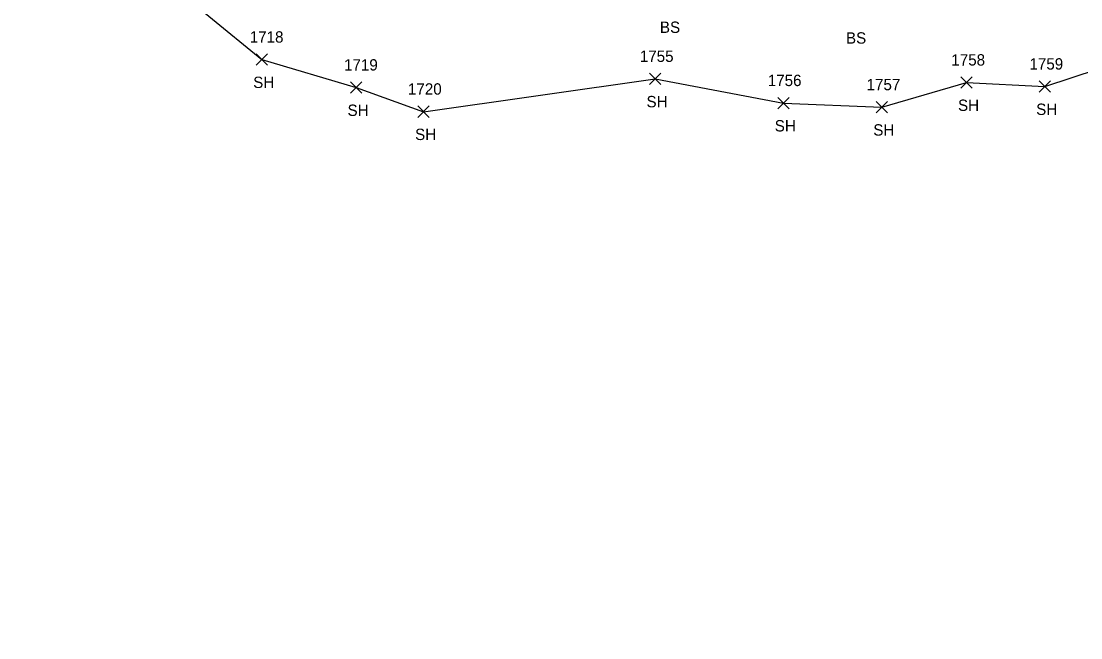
# Model space of a CAD drawing. Extents: x 1754529 to 1755810, y 621660 to 624656.
# Drawn here: x 1755027.6 to 1755214.3, y 623764.8 to 623873.5 of the extents above; entities that cross this region are included whole.
import ezdxf

# ---------------------------------------------------------------- set-up
doc = ezdxf.new("R2010")
doc.units = 0
for name, color, linetype in [('L_A', 7, 'Continuous'), ('L_I', 7, 'Continuous'), ('L_TIC', 7, 'Continuous'), ('LSOGP', 7, 'Continuous')]:
    doc.layers.add(name, color=color, linetype=linetype)

msp = doc.modelspace()

# ---------------------------------------------------------------- linework, layer by layer
at = {"layer": 'L_TIC'}
for points in [[(1755069.03, 623865.74), (1755071.03, 623867.74)], [(1755071.03, 623865.74), (1755069.03, 623867.74)], [(1755138.32, 623862.34), (1755140.32, 623864.34)], [(1755140.32, 623862.34), (1755138.32, 623864.34)], [(1755085.65, 623860.82), (1755087.65, 623862.82)], [(1755087.65, 623860.82), (1755085.65, 623862.82)], [(1755193.19, 623861.7), (1755195.19, 623863.7)], [(1755195.19, 623861.7), (1755193.19, 623863.7)], [(1755206.96, 623860.99), (1755208.96, 623862.99)], [(1755208.96, 623860.99), (1755206.96, 623862.99)], [(1755160.91, 623858.08), (1755162.91, 623860.08)], [(1755162.91, 623858.08), (1755160.91, 623860.08)], [(1755178.26, 623857.35), (1755180.26, 623859.35)], [(1755180.26, 623857.35), (1755178.26, 623859.35)], [(1755097.54, 623856.57), (1755099.54, 623858.57)], [(1755099.54, 623856.57), (1755097.54, 623858.57)]]:
    msp.add_lwpolyline(points, dxfattribs=at)
at = {"layer": 'LSOGP'}
msp.add_lwpolyline([(1755004.07, 623910.86), (1755037.03, 623891.65), (1755051.38, 623882.08), (1755070.03, 623866.74), (1755086.65, 623861.82), (1755098.54, 623857.57), (1755139.32, 623863.34), (1755161.91, 623859.08), (1755179.26, 623858.35), (1755194.19, 623862.7), (1755207.96, 623861.99), (1755217.43, 623865.11), (1755235.99, 623865.05), (1755250.43, 623863.91), (1755263.55, 623860.65), (1755279.26, 623833.69), (1755282.84, 623818.8), (1755283.41, 623777.57), (1755283.62, 623765.66), (1755287.66, 623764.84), (1755327.27, 623772.06), (1755352.63, 623769.93), (1755354.61, 623769.01), (1755434.62, 623771.42)], dxfattribs=at)

# ---------------------------------------------------------------- texts
at = {"layer": 'L_A'}
for s, p in [('BS', (1755140.16, 623871.45)), ('BS', (1755172.94, 623869.56)), ('SH', (1755068.51, 623861.74)), ('SH', (1755085.13, 623856.82)), ('SH', (1755137.8, 623858.34)), ('SH', (1755192.68, 623857.7)), ('SH', (1755206.45, 623856.99)), ('SH', (1755160.39, 623854.08)), ('SH', (1755177.75, 623853.35)), ('SH', (1755097.03, 623852.57))]:
    msp.add_text(s, height=2, dxfattribs=at).set_placement(p)
at = {"layer": 'L_I'}
for s, p in [('1718', (1755067.9, 623869.74)), ('1755', (1755136.62, 623866.34)), ('1719', (1755084.51, 623864.82)), ('1758', (1755191.5, 623865.7)), ('1759', (1755205.26, 623864.99)), ('1720', (1755095.77, 623860.57)), ('1756', (1755159.16, 623862.08)), ('1757', (1755176.57, 623861.35))]:
    msp.add_text(s, height=2, dxfattribs=at).set_placement(p)

doc.saveas('drawing.dxf')
